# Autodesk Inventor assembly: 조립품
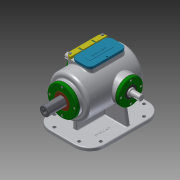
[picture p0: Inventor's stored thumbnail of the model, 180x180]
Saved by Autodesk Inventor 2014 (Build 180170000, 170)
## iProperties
Created: 2019-10
Part Number: 조립품
Document SubType Name: Assembly
Designer: kh
Mass: 7796.15 g
Surface Area: 4928.16 cm^2
Volume: 2172.9 cm^3
Density: 3.58791 g/cm^3
Author: kh
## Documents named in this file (17)
- C:\Users\kh\Desktop\391004V1007\조립품.iam
- C:\Users\kh\Desktop\391004V1007\본체.ipt
- C:\Users\kh\Desktop\391004V1007\가변스프링.ipt
- C:\Users\kh\Desktop\391004V1007\개스킷 A.ipt
- C:\Users\kh\Desktop\391004V1007\개스킷 B.ipt
- C:\Users\kh\Desktop\391004V1007\고정플레이트.ipt
- C:\Users\kh\Desktop\391004V1007\베어링 6205.ipt
- 베어링 6205.ipt
- C:\Users\kh\Desktop\391004V1007\볼트 M4x0.7.ipt
- C:\Users\kh\Desktop\391004V1007\부시.ipt
- C:\Users\kh\Desktop\391004V1007\상부커버.ipt
- C:\Users\kh\Desktop\391004V1007\슬라이드 커버.ipt
- C:\Users\kh\Desktop\391004V1007\슬라이드.ipt
- C:\Users\kh\Desktop\391004V1007\오일 실 25 38 8.ipt
- C:\Users\kh\Desktop\391004V1007\육각머리볼트 M4.ipt
- C:\Users\kh\Desktop\391004V1007\축 커버.ipt
- C:\Users\kh\Desktop\391004V1007\편심축.ipt
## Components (17 placed, 5 different names)
1. 가변스프링:1 — Mate:16, Mate:17, Mate:21
2. 개스킷 A:1 — Insert:12, Mate:9, Mate:10, Insert:14
3. 개스킷 B:1 — Insert:6, Mate:1, Mate:2, Insert:7
4. 고정플레이트:1 — Mate:11, Mate:12, Mate:13, Mate:15, Insert:16, Insert:17
5. 개스킷 B:2 — Insert:8, Mate:5, Mate:6, Insert:9
6. M4x0.7:2 — Insert:10, Angle:3
7. M4x0.7:3
8. M4x0.7:4
9. M4x0.7:5
10. M4x0.7:1 — Insert:11, Angle:4
11. M4x0.7:6
12. M4x0.7:7
13. M4x0.7:8
14. M4x0.7:9 — Insert:15, Angle:6
15. M4x0.7:10
16. M4x0.7:11
17. M4x0.7:12
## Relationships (27: Mate 13, Insert 11, Angle 3)
- Insert:6: 개스킷 B:1
- Mate:1: 개스킷 B:1
- Mate:2: 개스킷 B:1
- Insert:7: 개스킷 B:1
- Insert:8: 개스킷 B:2
- Mate:5: 개스킷 B:2
- Mate:6: 개스킷 B:2
- Insert:9: 개스킷 B:2
- Insert:10: M4x0.7:2
- Angle:3: M4x0.7:2
- Insert:11: M4x0.7:1
- Angle:4: M4x0.7:1
- Insert:12: 개스킷 A:1
- Mate:9: 개스킷 A:1
- Mate:10: 개스킷 A:1
- Mate:11: 고정플레이트:1
- Mate:12: 고정플레이트:1
- Mate:13: 고정플레이트:1
- Mate:15: 고정플레이트:1
- Mate:16: 가변스프링:1
- Mate:17: 가변스프링:1
- Insert:14: 개스킷 A:1
- Insert:15: M4x0.7:9
- Angle:6: M4x0.7:9
- Insert:16: 고정플레이트:1
- Insert:17: 고정플레이트:1
- Mate:21: 가변스프링:1
